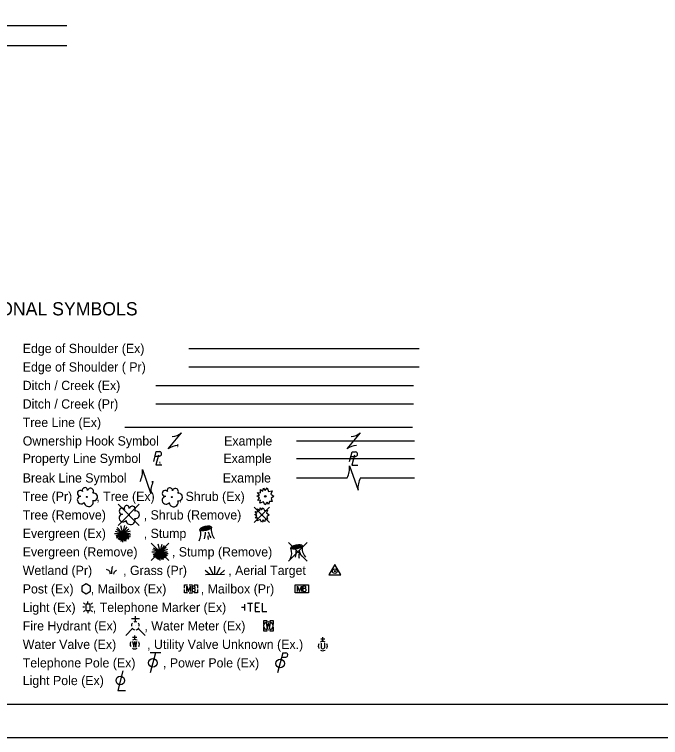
# Model space of a CAD drawing. Extents: x 0 to 34, y 0 to 22.
# Drawn here: x 8.18 to 17.96, y 0 to 10.95 of the extents above; entities that cross this region are included whole.
import ezdxf

# ---------------------------------------------------------------- set-up
doc = ezdxf.new("R2010")
doc.units = 0
for name, color, linetype in [('SH_Border', 7, 'Continuous'), ('SH_Cut_Line', 7, 'Continuous'), ('SH_Data', 7, 'Continuous'), ('SH_Text', 7, 'Continuous')]:
    doc.layers.add(name, color=color, linetype=linetype)

msp = doc.modelspace()

# ---------------------------------------------------------------- linework, layer by layer
at = {"layer": 'SH_Border'}
msp.add_lwpolyline([(1.5, 21.5), (33.5, 21.5), (33.5, 0.5), (1.5, 0.5)], close=True, dxfattribs=at)
at = {"layer": 'SH_Cut_Line'}
msp.add_lwpolyline([(0, 0), (34, 0), (34, 22), (0, 22)], close=True, dxfattribs=at)
at = {"layer": 'SH_Data'}
for p, q in [((8.976, 10.773), (7.726, 10.773)), ((8.976, 10.473), (7.726, 10.473))]:
    msp.add_line(p, q, dxfattribs=at)
at = {"layer": 'SH_Text'}
for p, q in [((10.822, 5.891), (14.306, 5.891)), ((10.822, 5.611), (14.306, 5.611)), ((10.322, 5.331), (14.222, 5.331)), ((10.322, 5.051), (14.222, 5.051)), ((9.854, 4.701), (14.204, 4.701)), ((10.509, 4.371), (10.709, 4.611)), ((13.217, 4.371), (13.417, 4.611)), ((10.609, 4.491), (10.609, 4.491)), ((12.452, 4.491), (14.234, 4.491)), ((13.317, 4.491), (13.317, 4.491)), ((10.309, 4.26), (10.374, 4.26)), ((10.35, 4.229), (10.35, 4.229)), ((12.452, 4.227), (14.234, 4.227)), ((13.275, 4.256), (13.34, 4.256)), ((13.315, 4.225), (13.315, 4.225)), ((10.117, 4.06), (10.247, 3.692)), ((13.252, 4.116), (13.382, 3.747)), ((10.182, 3.876), (10.182, 3.876)), ((12.452, 3.931), (13.217, 3.931)), ((13.317, 3.932), (13.317, 3.932)), ((13.417, 3.931), (14.234, 3.931)), ((9.75, 3.532), (10.07, 3.211)), ((10.07, 3.532), (9.75, 3.211)), ((11.809, 3.487), (12.04, 3.256)), ((12.04, 3.487), (11.809, 3.256)), ((9.91, 3.371), (9.91, 3.371)), ((11.925, 3.371), (11.925, 3.371)), ((9.82, 3.091), (9.733, 3.178)), ((9.82, 3.091), (9.79, 3.207)), ((9.82, 3.091), (9.852, 3.209)), ((9.82, 3.091), (9.887, 3.188)), ((9.697, 3.091), (9.82, 3.091)), ((9.82, 3.091), (9.71, 3.121)), ((9.82, 3.091), (9.713, 3.052)), ((9.82, 3.091), (9.721, 3.034)), ((9.82, 3.091), (9.723, 3.149)), ((9.82, 3.091), (9.723, 3.016)), ((9.82, 3.091), (9.747, 3.005)), ((9.82, 3.091), (9.762, 2.991)), ((9.82, 3.091), (9.779, 2.983)), ((9.82, 3.091), (9.789, 2.97)), ((9.82, 3.091), (9.807, 2.976)), ((9.82, 3.091), (9.912, 3.161)), ((9.82, 3.091), (9.939, 3.131)), ((9.82, 3.091), (9.933, 3.094)), ((9.82, 2.96), (9.82, 3.091)), ((9.82, 3.091), (9.843, 2.975)), ((9.82, 3.091), (9.869, 2.975)), ((9.82, 3.091), (9.884, 2.996)), ((9.82, 3.091), (9.91, 3.003)), ((9.82, 3.091), (9.916, 3.027)), ((9.82, 3.091), (9.932, 3.043)), ((9.82, 3.091), (9.941, 3.067)), ((11.094, 3.091), (11.094, 3.091)), ((10.251, 2.945), (10.518, 2.678)), ((10.518, 2.945), (10.251, 2.678)), ((10.384, 2.811), (10.287, 2.869)), ((10.384, 2.811), (10.297, 2.899)), ((10.384, 2.811), (10.354, 2.927)), ((10.384, 2.811), (10.416, 2.929)), ((10.384, 2.811), (10.451, 2.909)), ((10.384, 2.811), (10.476, 2.882)), ((10.384, 2.811), (10.503, 2.852)), ((12.331, 2.951), (12.609, 2.672)), ((12.609, 2.951), (12.331, 2.672)), ((10.261, 2.811), (10.384, 2.811)), ((10.384, 2.811), (10.274, 2.841)), ((10.384, 2.811), (10.277, 2.772)), ((10.384, 2.811), (10.285, 2.754)), ((10.384, 2.811), (10.287, 2.737)), ((10.384, 2.811), (10.311, 2.725)), ((10.384, 2.811), (10.326, 2.711)), ((10.384, 2.811), (10.343, 2.703)), ((10.384, 2.811), (10.353, 2.69)), ((10.384, 2.811), (10.371, 2.697)), ((10.384, 2.811), (10.497, 2.814)), ((10.384, 2.68), (10.384, 2.811)), ((10.384, 2.811), (10.407, 2.696)), ((10.384, 2.811), (10.433, 2.695)), ((10.384, 2.811), (10.448, 2.717)), ((10.384, 2.811), (10.474, 2.723)), ((10.384, 2.811), (10.48, 2.748)), ((10.384, 2.811), (10.496, 2.763)), ((10.384, 2.811), (10.505, 2.788)), ((10.384, 2.811), (10.384, 2.811)), ((12.47, 2.811), (12.47, 2.811)), ((12.47, 2.811), (12.47, 2.811)), ((11.137, 2.47), (11.069, 2.527)), ((11.186, 2.471), (11.134, 2.577)), ((11.216, 2.471), (11.214, 2.597)), ((11.246, 2.472), (11.295, 2.579)), ((11.295, 2.473), (11.361, 2.532)), ((11.07, 2.469), (11.362, 2.474)), ((10.827, 2.313), (10.877, 2.313)), ((10.827, 2.19), (10.877, 2.19)), ((10.853, 2.251), (10.853, 2.251)), ((12.531, 2.251), (12.531, 2.251)), ((9.241, 1.972), (9.214, 1.972)), ((9.245, 2.02), (9.226, 2.039)), ((9.293, 2.035), (9.293, 2.062)), ((9.293, 1.971), (9.293, 1.971)), ((9.36, 2.039), (9.341, 2.02)), ((9.372, 1.972), (9.345, 1.972)), ((11.666, 1.971), (11.616, 1.971)), ((11.666, 1.921), (11.666, 2.021)), ((9.245, 1.923), (9.226, 1.904)), ((9.293, 1.907), (9.293, 1.881)), ((9.36, 1.904), (9.341, 1.923)), ((10.071, 1.795), (9.951, 1.795)), ((10.011, 1.752), (10.011, 1.838)), ((9.969, 1.649), (9.865, 1.545)), ((10.011, 1.691), (10.011, 1.691)), ((10.011, 1.691), (10.011, 1.691)), ((10.054, 1.649), (10.158, 1.545)), ((12.025, 1.691), (12.025, 1.691)), ((10.002, 1.481), (10.002, 1.545)), ((10.034, 1.513), (9.97, 1.513)), ((12.88, 1.487), (12.816, 1.487)), ((12.821, 1.428), (12.821, 1.359)), ((12.848, 1.455), (12.848, 1.519)), ((12.875, 1.428), (12.875, 1.359)), ((10.002, 1.411), (10.002, 1.411)), ((12.848, 1.385), (12.848, 1.385)), ((10.395, 1.281), (10.235, 1.281)), ((10.315, 1.281), (10.235, 0.981)), ((12.244, 1.281), (12.164, 0.981)), ((12.227, 1.218), (12.287, 1.218)), ((12.244, 1.281), (12.287, 1.281))]:
    msp.add_line(p, q, dxfattribs=at)
for points in [[(10.288, 4.181), (10.328, 4.329), (10.379, 4.329)], [(10.363, 4.277), (10.323, 4.129), (10.411, 4.129)], [(13.254, 4.177), (13.293, 4.325), (13.345, 4.325)], [(13.328, 4.273), (13.289, 4.125), (13.376, 4.125)], [(11.973, 3.742), (12.004, 3.779), (12.024, 3.726), (12.079, 3.735), (12.062, 3.684), (12.109, 3.655), (12.066, 3.618), (12.079, 3.572), (12.041, 3.576), (12.025, 3.53), (12.004, 3.565), (11.97, 3.524), (11.948, 3.568), (11.897, 3.547), (11.907, 3.594), (11.866, 3.59), (11.89, 3.629), (11.851, 3.657), (11.888, 3.671), (11.858, 3.711), (11.905, 3.705), (11.903, 3.757), (11.941, 3.729), (11.951, 3.778), (11.973, 3.742)], [(11.921, 3.448), (11.947, 3.48), (11.964, 3.435), (12.011, 3.443), (11.996, 3.4), (12.036, 3.374), (12, 3.343), (12.011, 3.304), (11.979, 3.307), (11.965, 3.268), (11.947, 3.298), (11.918, 3.263), (11.9, 3.301), (11.856, 3.282), (11.864, 3.322), (11.83, 3.319), (11.85, 3.352), (11.817, 3.377), (11.849, 3.388), (11.823, 3.422), (11.863, 3.417), (11.861, 3.461), (11.893, 3.437), (11.902, 3.479), (11.921, 3.448)], [(9.2, 2.214), (9.265, 2.176), (9.33, 2.214), (9.33, 2.289), (9.265, 2.326), (9.2, 2.289), (9.2, 2.214)], [(10.753, 2.264), (10.753, 2.313), (10.801, 2.313)], [(10.903, 2.313), (10.953, 2.313), (10.953, 2.264)], [(10.801, 2.19), (10.753, 2.19), (10.753, 2.239)], [(10.788, 2.211), (10.788, 2.291), (10.817, 2.211), (10.845, 2.291), (10.845, 2.211)], [(10.904, 2.255), (10.907, 2.258), (10.909, 2.26), (10.91, 2.262), (10.911, 2.263), (10.912, 2.266), (10.913, 2.268), (10.914, 2.272), (10.914, 2.274), (10.914, 2.276), (10.913, 2.28), (10.912, 2.283), (10.91, 2.286), (10.907, 2.288), (10.905, 2.29), (10.903, 2.29), (10.9, 2.291), (10.869, 2.291), (10.869, 2.211), (10.904, 2.211), (10.908, 2.214), (10.912, 2.217), (10.915, 2.222), (10.917, 2.228), (10.918, 2.234), (10.918, 2.237), (10.916, 2.241), (10.914, 2.247), (10.911, 2.251), (10.904, 2.255), (10.869, 2.255)], [(10.953, 2.239), (10.953, 2.19), (10.903, 2.19)], [(12.466, 2.211), (12.466, 2.291), (12.495, 2.211), (12.523, 2.291), (12.523, 2.211)], [(12.582, 2.255), (12.585, 2.258), (12.587, 2.26), (12.588, 2.262), (12.589, 2.263), (12.59, 2.266), (12.591, 2.268), (12.592, 2.272), (12.592, 2.274), (12.592, 2.276), (12.591, 2.28), (12.59, 2.283), (12.588, 2.286), (12.585, 2.288), (12.583, 2.29), (12.581, 2.29), (12.578, 2.291), (12.547, 2.291), (12.547, 2.211), (12.582, 2.211), (12.586, 2.214), (12.59, 2.217), (12.593, 2.222), (12.595, 2.228), (12.596, 2.234), (12.596, 2.237), (12.595, 2.241), (12.592, 2.247), (12.589, 2.251), (12.582, 2.255), (12.547, 2.255)], [(11.707, 2.034), (11.784, 2.034)], [(11.746, 2.034), (11.746, 1.909)], [(11.892, 2.034), (11.824, 2.034), (11.824, 1.909), (11.897, 1.909)], [(11.824, 1.972), (11.872, 1.972)], [(11.931, 2.034), (11.931, 1.909), (11.999, 1.909)], [(12.005, 1.766), (11.95, 1.766), (11.95, 1.711)], [(12.1, 1.711), (12.1, 1.766), (12.045, 1.766)], [(11.95, 1.671), (11.95, 1.616), (12.005, 1.616)], [(11.991, 1.736), (12.008, 1.646), (12.025, 1.736), (12.041, 1.646), (12.058, 1.736)], [(12.045, 1.616), (12.1, 1.616), (12.1, 1.671)], [(9.97, 1.452), (9.986, 1.366), (10.002, 1.452), (10.018, 1.366), (10.034, 1.452)], [(9.822, 1.01), (9.744, 0.711), (9.862, 0.711)]]:
    msp.add_lwpolyline(points, dxfattribs=at)
for points in [[(12.939, 2.461), (13.119, 2.461), (13.029, 2.622)], [(12.431, 2.313), (12.631, 2.313), (12.631, 2.19), (12.431, 2.19)], [(9.26, 1.921), (9.326, 1.921), (9.326, 2.021), (9.26, 2.021)]]:
    msp.add_lwpolyline(points, close=True, dxfattribs=at)
for centre, radius in [((9.277, 3.643), 0.0084), ((10.562, 3.64), 0.0072), ((11.978, 3.651), 0.0115), ((9.91, 3.371), 0.0072), ((11.925, 3.371), 0.00979), ((13.029, 2.519), 0.035), ((13.029, 2.519), 0.008), ((12.025, 1.691), 0.0675), ((10.275, 1.131), 0.065), ((12.201, 1.121), 0.065), ((9.783, 0.863), 0.065)]:
    msp.add_circle(centre, radius, dxfattribs=at)
for centre, radius, start, end in [((10.551, 4.826), 0.267, 273.6945, 306.337), ((13.259, 4.826), 0.267, 273.6945, 306.337), ((10.667, 4.157), 0.267, 93.6945, 126.337), ((13.375, 4.157), 0.267, 93.6945, 126.337), ((10.374, 4.295), 0.0345, 270.471, 81.3281), ((13.34, 4.291), 0.0345, 270.471, 81.3281), ((9.785, 4.028), 0.334, 332.9422, 5.5848), ((12.92, 4.083), 0.334, 332.9422, 5.5848), ((10.579, 3.724), 0.334, 152.9422, 185.5848), ((13.714, 3.78), 0.334, 152.9422, 185.5848), ((9.178, 3.699), 0.0441, 39.0625, 279.5412), ((9.247, 3.744), 0.0395, 354.0047, 205.9741), ((9.332, 3.728), 0.0466, 323.83, 165.0376), ((10.462, 3.696), 0.0441, 39.0625, 279.5412), ((10.532, 3.741), 0.0395, 354.0047, 205.9741), ((10.616, 3.725), 0.0466, 323.83, 165.0376), ((9.191, 3.597), 0.0592, 96.1722, 320.5737), ((9.381, 3.644), 0.0574, 259.1453, 101.4596), ((10.476, 3.593), 0.0592, 96.1722, 320.5737), ((10.665, 3.641), 0.0574, 259.1453, 101.4596), ((9.305, 3.565), 0.0685, 184.9476, 19.4572), ((9.88, 3.472), 0.0395, 354.0047, 205.9741), ((10.59, 3.562), 0.0685, 184.9476, 19.4572), ((9.811, 3.427), 0.0441, 39.0625, 279.5412), ((9.965, 3.456), 0.0466, 323.83, 165.0376), ((10.014, 3.373), 0.0574, 259.1453, 101.4596), ((9.824, 3.325), 0.0592, 96.1722, 320.5737), ((9.938, 3.293), 0.0685, 184.9476, 19.4572), ((11.374, 3.149), 0.215, 171.4106, 219.9194), ((10.802, 3.074), 0.2, 331.5338, 20.9269), ((10.818, 3.093), 0.253, 340.7938, 3.5481), ((11.419, 3.194), 0.316, 194.9653, 212.1216), ((11.289, 3.051), 0.182, 178.7926, 197.1224), ((12.178, 2.794), 0.2, 331.5338, 20.9269), ((12.75, 2.869), 0.215, 171.4106, 219.9194), ((12.194, 2.813), 0.253, 340.7938, 3.5481), ((12.665, 2.771), 0.182, 178.7926, 197.1224), ((12.795, 2.914), 0.316, 194.9653, 212.1216), ((10.011, 1.691), 0.06, 140.021, 184.0629), ((10.011, 1.691), 0.06, 211.8788, 255.8479), ((10.011, 1.691), 0.06, 68.1395, 112.038), ((10.011, 1.691), 0.06, 283.8239, 329.9097), ((10.011, 1.691), 0.06, 356.0165, 39.9889), ((10.002, 1.412), 0.07, 150.0184, 209.9816), ((10.002, 1.412), 0.07, 60.0184, 120.0157), ((10.002, 1.412), 0.07, 330.0184, 29.9816), ((12.848, 1.385), 0.07, 60.0184, 120.0157), ((10.002, 1.412), 0.07, 239.9843, 299.9816), ((12.848, 1.385), 0.07, 150.0184, 209.9816), ((12.848, 1.385), 0.07, 239.9843, 299.9816), ((12.848, 1.372), 0.03, 205.1924, 334.8076), ((12.848, 1.385), 0.07, 330.0184, 29.9816), ((12.287, 1.25), 0.0319, 268.8767, 91.1233)]:
    msp.add_arc(centre, radius, start, end, dxfattribs=at)
for centre, major_axis in [((11.075, 3.167), (0.0868, 0.0187)), ((11.075, 3.167), (0.0651, 0.0141)), ((11.075, 3.167), (0.0488, 0.0105)), ((11.075, 3.167), (0.0275, 0.0059)), ((11.075, 3.167), (0.0154, 0.0033)), ((12.451, 2.887), (0.0868, 0.0187)), ((12.451, 2.887), (0.0651, 0.0141)), ((12.451, 2.887), (0.0488, 0.0105)), ((12.451, 2.887), (0.0275, 0.0059)), ((12.451, 2.887), (0.0154, 0.0033))]:
    msp.add_ellipse(centre, major_axis=major_axis, ratio=0.36865, dxfattribs=at)
for points in [[(9.569, 2.547), (9.611, 2.529), (9.628, 2.476)], [(9.657, 2.48), (9.657, 2.527), (9.662, 2.572), (9.671, 2.593)], [(9.684, 2.473), (9.696, 2.511), (9.726, 2.535)]]:
    msp.add_spline(points, degree=3, dxfattribs=at)

# ---------------------------------------------------------------- texts
for s, height, p in [('CONVENTIONAL SYMBOLS', 0.2, (6.567, 6.391)), ('Edge of Shoulder (Ex)', 0.14, (8.306, 5.821)), ('Edge of Shoulder ( Pr)', 0.14, (8.306, 5.541)), ('Ditch / Creek (Ex)', 0.14, (8.306, 5.261)), ('Ditch / Creek (Pr)', 0.14, (8.306, 4.981)), ('Tree Line (Ex)', 0.14, (8.306, 4.701)), ('Ownership Hook Symbol     ,             Example', 0.14, (8.306, 4.421)), ('Property Line Symbol     ,                  Example', 0.14, (8.306, 4.157)), ('Break Line Symbol       ,                    Example', 0.14, (8.306, 3.861)), ('Tree (Pr)       , Tree (Ex)       , Shrub (Ex)', 0.14, (8.306, 3.581)), ('Tree (Remove)           , Shrub (Remove)', 0.14, (8.306, 3.301)), ('Evergreen (Ex)           , Stump ', 0.14, (8.306, 3.021)), ('Evergreen (Remove)          , Stump (Remove)', 0.14, (8.306, 2.741)), ('Wetland (Pr)         , Grass (Pr)            , Aerial Target    ', 0.14, (8.306, 2.461)), ('Post (Ex)     , Mailbox (Ex)          , Mailbox (Pr)', 0.14, (8.306, 2.181)), ('Light (Ex)     , Telephone Marker (Ex)     ', 0.14, (8.306, 1.901)), ('Fire Hydrant (Ex)        , Water Meter (Ex)', 0.14, (8.306, 1.621)), ('Water Valve (Ex)         , Utility Valve Unknown (Ex.)', 0.14, (8.306, 1.341)), ('Telephone Pole (Ex)        , Power Pole (Ex)', 0.14, (8.306, 1.061)), ('Light Pole (Ex)     ', 0.14, (8.306, 0.794))]:
    msp.add_text(s, height=height, dxfattribs=at).set_placement(p)

doc.saveas('drawing.dxf')
